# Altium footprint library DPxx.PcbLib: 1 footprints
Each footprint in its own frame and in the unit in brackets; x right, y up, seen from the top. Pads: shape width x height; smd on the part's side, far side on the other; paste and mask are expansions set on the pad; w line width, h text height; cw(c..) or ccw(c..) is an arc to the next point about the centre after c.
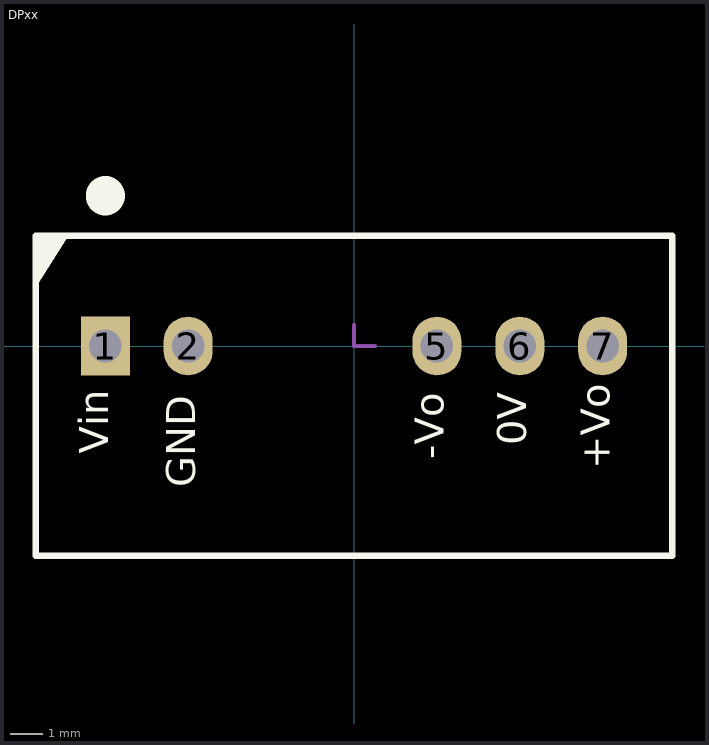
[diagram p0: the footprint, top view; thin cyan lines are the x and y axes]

## DPxx [mm]
height 12.5
pads (5):
  rect 1.5x1.8 hole 1: 1(-7.62,0)
  oval 1.5x1.8 hole 1: 2(-5.08,0) 5(2.54,0) 6(5.08,0) 7(7.62,0)
Top Overlay:
  circle w1: c-7.62,4.605 r0.1
  region: -9.75,1.794 -9.75,3.38 -8.756,3.38
  lines w0.2: -9.75,-6.42 -9.75,3.38 9.75,3.38 9.75,-6.42 -9.75,-6.42
  text "+Vo" at 8.128,-3.775 h1.52
  text "0V" at 5.568,-3.037 h1.52
  text "-Vo" at 3.048,-3.465 h1.52
  text "GND" at -4.572,-4.321 h1.52
  text "Vin" at -7.239,-3.307 h1.52
Mechanical 15:
  lines w0.127: 0,0.635 0,0 0.635,0
3D body: height 12.5, standoff 0, extent -9.75,-6.42 9.75,3.38
3D body "zhenjao01.stp": height 8.36, standoff -4.08, extent -8.32,-1.48 -6.92,0.12
3D body "zhenjao01.stp": height 8.36, standoff -4.08, extent -5.78,-1.48 -4.38,0.12
3D body "zhenjao01.stp": height 8.36, standoff -4.08, extent 1.84,-1.48 3.24,0.12
3D body "zhenjao01.stp": height 8.36, standoff -4.08, extent 4.38,-1.48 5.78,0.12
3D body "zhenjao01.stp": height 8.36, standoff -4.08, extent 6.92,-1.48 8.32,0.12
